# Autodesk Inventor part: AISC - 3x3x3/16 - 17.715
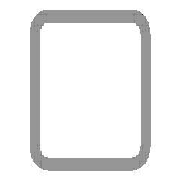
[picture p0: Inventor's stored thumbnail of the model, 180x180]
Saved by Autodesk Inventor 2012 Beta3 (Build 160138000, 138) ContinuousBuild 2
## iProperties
IsCustomPart: 1
Created: 2011-01
Part Number: AISC - 3x3x3/16 - 17.715
Material: Steel, Mild
Description: Tube
Document SubType Name: Modeling
Standard: ANSI
Designer: Beta-8540w
Standards Organization: ANSI
Language: en-US
Size Designation: 3x3x3/16
Categories: <MemberInstance><Categories><Category DisplayName="Structural Shapes" InternalName="089c4875-fa83-4c05-b084-43b9cc11f5ed" Mnemonic="GRDR"><CategoryParameter Dis
Stock Number: 3x3x3/16
Density: 7.86 g/cm^3
G_L: 17.715 in
G_W: 3.000 in
G_H: 3.000 in
_CCFamilyMember: 9
_CCFamilyDisplayName: ANSI AISC (Square) - Tube
_FrameMemberDoc: Frame Member File
_Version: 15.0.0
_GetPNFromCC: 1
Author: Beta-8540w
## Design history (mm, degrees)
node "Start plane"
node "End plane"
sketch "Sketch"
  geometry: L1 (-38.1, -28.575)-(-38.1, 28.575); L2 (-28.575, 38.1)-(28.575, 38.1); L3 (38.1, 28.575)-(38.1, -28.575); L4 (28.575, -38.1)-(-28.575, -38.1); L5 (-28.575, 33.337)-(28.575, 33.338); L6 (33.338, 28.575)-(33.338, -28.575); L7 (28.575, -33.337)-(-28.575, -33.338); L8 (-33.338, -28.575)-(-33.338, 28.575); L9 (0, 56.102)-(0, -56.102) reference; L10 (-56.102, 0)-(56.102, 0) reference; A1 r 9.525 centre (-28.575, -28.575) between (-38.1, -28.575) and (-28.575, -38.1); A2 r 9.525 centre (-28.575, 28.575) between (-28.575, 38.1) and (-38.1, 28.575); A3 r 9.525 centre (28.575, 28.575) between (38.1, 28.575) and (28.575, 38.1); A4 r 9.525 centre (28.575, -28.575) between (28.575, -38.1) and (38.1, -28.575); A5 r 4.763 centre (-28.575, 28.575) between (-28.575, 33.337) and (-33.338, 28.575); A6 r 4.763 centre (28.575, 28.575) between (33.338, 28.575) and (28.575, 33.338); A7 r 4.763 centre (28.575, -28.575) between (28.575, -33.337) and (33.338, -28.575); A8 r 4.763 centre (-28.575, -28.575) between (-33.338, -28.575) and (-28.575, -33.338)
  constraints: 16 end point, 16 point on circle, 8 centre point, 8 tangent, 4 parallel, 3 equal radius, 2 perpendicular, 7 other
  dimensions: "d10" = 76.2 distance between parallel lines of L2 L4 (= G_H); "d11" = 76.2 distance between parallel lines of L1 L3 (= G_W); "d12" = 4.7625 distance between parallel lines of L3 L6 (= G_T); "d15" = 38.1 distance between parallel lines of L2 L10 (= 0.5 x d10); "d16" = 38.1 distance between parallel lines of L9 L3 (= 0.5 x d11); "d17" = 9.525 radius of A1 (= G_IR)
extrude "Body" new body sketch "Sketch" stored distance "d3" = 449.97309 (= G_L); taper "d4" = 0 deg
node "Driven Length"
  sketch "Sketch3"
    geometry: L1 (0, 0)-(10, 0) reference
    constraints: 2 end point, 1 horizontal
  workplane "Work Plane3"
  sketch "Sketch4"
    geometry: L1 (-2, 0)-(12, 0) reference; L2 (-2, 449.973)-(12, 449.973) reference
    dimensions: "d19" = 449.97309 distance between parallel lines of L1 L2 (derived)
body "Solid1"
other parameters: "G_W" = 76.2 [user parameter; used in 1 equation term], "G_H" = 76.2 [user parameter; used in 1 equation term], "G_T" = 4.7625 [user parameter; used in 1 equation term], "G_IR" = 9.525 [user parameter; used in 1 equation term], "G_L" = 449.97309 (= d19) [user parameter; used in 1 equation term], "G_OFFSET_START" = 0 [user parameter; used in 1 equation term], "G_OFFSET_END" = 0 [user parameter; used in 1 equation term], "d13" = 0 (computed from G_OFFSET_START), "d14" = 449.97309 (= G_OFFSET_END + B_L), "B_L" = 449.97309 [user parameter; used in 1 equation term], "d18" = 90 deg
